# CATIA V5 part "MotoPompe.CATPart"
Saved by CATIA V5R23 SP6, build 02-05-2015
Part number: MotoPompe
Publications: "CATRouFace1", "CATRouCenter1", "CATRouCircular1", "CATRouDatumPt1", "CATRouFace2", "CATRouCenter2", "CATRouCircular2", "CATRouDatumPt2"
Bounding box of the stored display mesh (mm): x -1200 to 1233.058, y -1160.359 to 1160.359, z -3900 to 3100
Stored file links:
  \\etu.ad.univ-lorraine.fr\bordron1\Documents\Parts EPR\MotoPompe.CATPart
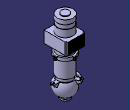
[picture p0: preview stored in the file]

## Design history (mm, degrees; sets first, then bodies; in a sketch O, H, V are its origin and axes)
AxisSystem1: origin (0, 0, 0), X (1, 0, 0), Y (0, 1, 0), Z (0, 0, 1)
Set1
  Point1: type Center, Curve edge [face of Pad8 from Sketch7.A1 | end face of Pad8]
  Line1: type PtDir, RefPoint Point1, Direction edge [XY plane of AxisSystem1 | ZX plane of AxisSystem1], Start -482, End 506
  Point2: type Center, Curve edge [face of Shaft1 from Sketch1.L18 | face of Shaft1 from Sketch1.L17]
  Line2: type PtDir, RefPoint Point2, Direction edge [ZX plane of AxisSystem1 | YZ plane of AxisSystem1], Start -1522, End 506
Body1 (main body)
  Sketch1 on YZ plane of AxisSystem1, origin (0, 0, 0), H (0, 1, 0), V (0, 0, 1)
    line L1 (-750, -300) -> (-750, -1900)
    reference intersected line E1 through (0, 0) direction (0, 1) from ZX plane of AxisSystem1
    line L2 (0, 3100) -> (-375, 3100)
    point P3 (0, 3100)
    line L3 (-375, 3100) -> (-375, 3020)
    line L4 (-375, 3020) -> (-750, 3020)
    point P6 (-750, 3020)
    line L5 (-750, 3020) -> (-750, 2620)
    line L6 (-750, 2620) -> (-710, 2620)
    line L7 (-710, 2620) -> (-710, 2220)
    line L8 (-710, 2220) -> (-750, 2220)
    point P10 (-750, 2220)
    line L9 (-750, 2220) -> (-750, 0)
    line L10 (-750, 0) -> (-900, 0)
    line L11 (-900, 0) -> (-900, -300)
    line L12 (-900, -300) -> (-750, -300)
    line L13 (-750, -1900) -> (-670, -1900)
    line L14 (-670, -1900) -> (-670, -2200)
    line L15 (-670, -2200) -> (-750, -2200)
    point P16 (-750, -2200)
    arc A1 centre (0, -2783.0952) radius 950 from (-750, -2200) to (-548.2292, -3558.9462) ccw
    point P17 (0, -2783.0952)
    line L16 (-442.5, -3763.1175) -> (-442.5, -3900)
    line L17 (-442.5, -3900) -> (-385, -3900)
    line L18 (-385, -3900) -> (-385, -3000)
    line L19 (-385, -3000) -> (0, -3000)
    point P21 (0, -3000)
    reference intersected line E2 through (0, 0) direction (-1, 0) from XY plane of AxisSystem1
    reference intersected line E3 through (0, 0) direction (0, 1) from ZX plane of AxisSystem1
    reference intersected line E4 through (0, 0) direction (0, 1) from ZX plane of AxisSystem1
    reference intersected line E5 through (0, 0) direction (-1, 0) from XY plane of AxisSystem1
    arc A2 centre (-692.5, -3763.1175) radius 250 from (-548.2292, -3558.9462) to (-442.5, -3763.1175) cw
    distance L1 E1 = 750
    distance L17 L2 = 7000
    length L1 = 1600
    length L14 = 300
    length L11 = 300
    length L5 = 400
    length L7 = 400
    distance L2 L4 = 80
    length L2 = 375
    distance L7 L5 = 40
    distance L11 L9 = 150
    distance L1 L14 = 80
    radius A1 = 950
    distance L18 E3 = 385
    distance L16 E4 = 442.5
    length L18 = 900
    distance L19 E5 = 3000
    radius A2 = 250
    vertical: L1 V, L3 V, L5 V, L7 V, L9 V, L11 V, L14 V, L16 V, L18 V
    coincidence: P3 V, P6 L1, P10 L1, P16 L1, P17 V, P21 V, L10 E2
    horizontal: L2 H, L4 H, L6 H, L8 H, L10 H, L12 H, L13 H, L15 H, L17 H, L19 H
    tangency: A2 L16, A2 A1
  Shaft1: profile Sketch1, axis edge [ZX plane of AxisSystem1 | YZ plane of AxisSystem1], angle 360
  Sketch2 on XY plane of AxisSystem1, origin (0, 0, 0), H (1, 0, 0), V (0, 1, 0)
    projected circle E1 centre (0, 0) radius 900 from edge [face of Shaft1 from Sketch1.L11 | face of Shaft1 from Sketch1.L10]
    projected arc E2 centre (0, 0) radius 900 from (885.6636, -160) to (885.6636, 160) ccw from edge [face of Shaft1 from Sketch1.L11 | face of Shaft1 from Sketch1.L10]
    line L1 (958.8327, 148.3022) -> (1044.2788, 76.6044)
    line L2 (958.8327, -148.3022) -> (1044.2788, -76.6044)
    point P2 (1044.2788, -76.6044)
    arc A1 centre (980, 0) radius 100 from (1044.2788, -76.6044) to (1044.2788, 76.6044) ccw
    point P3 (980, 0)
    point P4 (1044.2788, -76.6044)
    line L3 (885.6636, 160) -> (926.6933, 160)
    point P5 (885.6636, 160)
    line L4 (926.6933, -160) -> (885.6636, -160)
    point P6 (885.6636, -160)
    reference intersected line E3 through (0, 0) direction (-1, 0) from ZX plane of AxisSystem1
    arc A2 centre (926.6933, 110) radius 50 from (958.8327, 148.3022) to (926.6933, 160) ccw
    arc A3 centre (926.6933, -110) radius 50 from (958.8327, -148.3022) to (926.6933, -160) cw
    circle A4 centre (980, 0) radius 40
    angle L1 H = 40
    radius A1 = 100
    distance P3 O = 980
    distance L4 L3 = 320
    radius A2 = 50
    radius A3 = 50
    radius A4 = 40
    coincidence: P4 P2, P5 E1, P6 E1
    tangency: A1 L1, L2 A1, A2 L1, A2 L3, A3 L2, A3 L4
    symmetry: L2 L1 H, L4 L3 E3
    horizontal: L3 H, L4 H
  Pad1: profile Sketch2, direction (0, 0, -1), length 90
  Pad2: profile Sketch2, direction (0, 0, 1), up to face of Shaft1 from Sketch1.L12, opposite side length 210
  CircPattern1: of Pad1, Sketch2, Pad2, Sketch2, instances 4, angular step 90, axis from edge [ZX plane of AxisSystem1 | YZ plane of AxisSystem1]
  Sketch3 on YZ plane of AxisSystem1, origin (0, 0, 0), H (0, 1, 0), V (0, 0, 1)
    line L1 (-1100, 1550) -> (900, 1550)
    line L2 (900, 1550) -> (900, 450)
    line L3 (900, 450) -> (-1100, 450)
    line L4 (-1100, 450) -> (-1100, 1550)
    distance H L3 = 450
    length L4 = 1100
    distance L4 V = 1100
    distance L2 V = 900
    horizontal: L1 H, L3 H
    vertical: L2 V, L4 V
  Pad3: profile Sketch3, direction (1, 0, 0), length 900, mirrored extent
  Sketch4 on face of Pad3 from Sketch3.L2, origin (0, 900, 0), H (-1, 0, 0), V (0, 0, 1)
    projected line E1 (900, 1550) -> (-900, 1550) from edge [face of Pad3 from Sketch3.L1 | face of Pad3 from Sketch3.L2]
    projected line E2 (900, 450) -> (-900, 450) from edge [face of Pad3 from Sketch3.L2 | face of Pad3 from Sketch3.L3]
    point P5 (-787.626, 1550)
    point P6 (-787.626, 450)
    line L1 (-787.626, 1550) -> (0, 1550)
    point P7 (0, 1550)
    line L2 (-787.626, 450) -> (0, 450)
    point P8 (0, 450)
    point P9 (-714, 1490)
    point P10 (-714, 510)
    line L3 (-714, 510) -> (-655, 510)
    point P11 (0, 510)
    line L4 (-714, 1490) -> (-655, 1490)
    point P12 (0, 1490)
    line L5 (-655, 1490) -> (-655, 510)
    point P13 (-655, 1490)
    point P14 (-655, 510)
    line L6 (-633, 510) -> (-633, 1490)
    point P15 (-633, 510)
    point P16 (-633, 1490)
    line L7 (-563, 1490) -> (-563, 510)
    point P17 (-563, 1490)
    point P18 (-563, 510)
    line L8 (-541, 510) -> (-541, 1490)
    point P19 (-541, 510)
    point P20 (-541, 1490)
    line L9 (-471, 1490) -> (-471, 510)
    point P21 (-471, 1490)
    point P22 (-471, 510)
    line L10 (-449, 510) -> (-449, 1490)
    point P23 (-449, 510)
    point P24 (-449, 1490)
    line L11 (-379, 1490) -> (-379, 510)
    point P25 (-379, 1490)
    point P26 (-379, 510)
    line L12 (-357, 510) -> (-357, 1490)
    point P27 (-357, 510)
    point P28 (-357, 1490)
    line L13 (-287, 1490) -> (-287, 510)
    point P29 (-287, 1490)
    point P30 (-287, 510)
    line L14 (-265, 510) -> (-265, 1490)
    point P31 (-265, 510)
    point P32 (-265, 1490)
    line L15 (-195, 1490) -> (-195, 510)
    point P33 (-195, 1490)
    point P34 (-195, 510)
    line L16 (-173, 510) -> (-173, 1490)
    point P35 (-173, 510)
    point P36 (-173, 1490)
    line L17 (-103, 1490) -> (-103, 510)
    point P37 (-103, 1490)
    point P38 (-103, 510)
    line L18 (-81, 510) -> (-81, 1490)
    point P39 (-81, 510)
    point P40 (-81, 1490)
    line L19 (-714, 1490) -> (-714, 510)
    line L20 (-11, 1490) -> (-11, 510)
    point P41 (-11, 1490)
    point P42 (-11, 510)
    reference projected line E3 through (0, 0) direction (0, 1) from edge [ZX plane of AxisSystem1 | YZ plane of AxisSystem1]
    point P45 (787.626, 450)
    point P46 (787.626, 1550)
    line L21 (-633, 1490) -> (-563, 1490)
    line L22 (-541, 1490) -> (-471, 1490)
    line L23 (-449, 1490) -> (-379, 1490)
    line L24 (-357, 1490) -> (-287, 1490)
    line L25 (-265, 1490) -> (-195, 1490)
    line L26 (-173, 1490) -> (-103, 1490)
    line L27 (-81, 1490) -> (-11, 1490)
    line L28 (-81, 510) -> (-11, 510)
    line L29 (-173, 510) -> (-103, 510)
    line L30 (-265, 510) -> (-195, 510)
    line L31 (-357, 510) -> (-287, 510)
    line L32 (-449, 510) -> (-379, 510)
    line L33 (-541, 510) -> (-471, 510)
    line L34 (-633, 510) -> (-563, 510)
    reference intersected line E4 through (0, 0) direction (0, -1) from YZ plane of AxisSystem1
    point P49 (714, 1490)
    point P50 (714, 510)
    point P51 (0, 510)
    point P52 (0, 1490)
    point P53 (655, 1490)
    point P54 (655, 510)
    point P55 (633, 510)
    point P56 (633, 1490)
    point P57 (563, 1490)
    point P58 (563, 510)
    point P59 (541, 510)
    point P60 (541, 1490)
    point P61 (471, 1490)
    point P62 (471, 510)
    point P63 (449, 510)
    point P64 (449, 1490)
    point P65 (379, 1490)
    point P66 (379, 510)
    point P67 (357, 510)
    point P68 (357, 1490)
    point P69 (287, 1490)
    point P70 (287, 510)
    point P71 (265, 510)
    point P72 (265, 1490)
    point P73 (195, 1490)
    point P74 (195, 510)
    point P75 (173, 510)
    point P76 (173, 1490)
    point P77 (103, 1490)
    point P78 (103, 510)
    point P79 (81, 510)
    point P80 (81, 1490)
    point P81 (11, 1490)
    point P82 (11, 510)
    line L35 (714, 510) -> (655, 510)
    line L36 (714, 1490) -> (655, 1490)
    line L37 (655, 1490) -> (655, 510)
    line L38 (633, 510) -> (633, 1490)
    line L39 (563, 1490) -> (563, 510)
    line L40 (541, 510) -> (541, 1490)
    line L41 (471, 1490) -> (471, 510)
    line L42 (449, 510) -> (449, 1490)
    line L43 (379, 1490) -> (379, 510)
    line L44 (357, 510) -> (357, 1490)
    line L45 (287, 1490) -> (287, 510)
    line L46 (265, 510) -> (265, 1490)
    line L47 (195, 1490) -> (195, 510)
    line L48 (173, 510) -> (173, 1490)
    line L49 (103, 1490) -> (103, 510)
    line L50 (81, 510) -> (81, 1490)
    line L51 (714, 1490) -> (714, 510)
    line L52 (11, 1490) -> (11, 510)
    line L53 (633, 1490) -> (563, 1490)
    line L54 (541, 1490) -> (471, 1490)
    line L55 (449, 1490) -> (379, 1490)
    line L56 (357, 1490) -> (287, 1490)
    line L57 (265, 1490) -> (195, 1490)
    line L58 (173, 1490) -> (103, 1490)
    line L59 (81, 1490) -> (11, 1490)
    line L60 (81, 510) -> (11, 510)
    line L61 (173, 510) -> (103, 510)
    line L62 (265, 510) -> (195, 510)
    line L63 (357, 510) -> (287, 510)
    line L64 (449, 510) -> (379, 510)
    line L65 (541, 510) -> (471, 510)
    line L66 (633, 510) -> (563, 510)
    line L67 (-787.626, 1550) -> (-787.626, 450)
    line L68 (787.626, 1550) -> (787.626, 450)
    line L69 (0, 1550) -> (787.626, 1550)
    line L70 (787.626, 450) -> (0, 450)
    distance L5 L6 = 22
    distance L6 L7 = 70
    distance L8 L7 = 22
    distance L8 L9 = 70
    distance L9 L10 = 22
    distance L10 L11 = 70
    distance L11 L12 = 22
    distance L12 L13 = 70
    distance L13 L14 = 22
    distance L14 L15 = 70
    distance L15 L16 = 22
    distance L16 L17 = 70
    distance L17 L18 = 22
    distance L18 L20 = 70
    distance L20 P12 = 11
    distance L3 L2 = 60
    distance L4 L1 = 60
    coincidence: P5 E1, P6 E2, P11 V, P12 V, P15 L3, P16 L4, P17 L4, P19 L3, P20 L4, P21 L4, P23 L3, P24 L4, P25 L4, P29 L4, P31 L3, P32 L4, P33 L4, P35 L3, P36 L4, P37 L4, P39 L3, P40 L4, P41 L4, P42 L3, L4 P28, L4 L21, L21 L22, L22 L23, L23 L24, L24 L25, L25 L26, L26 L27, L3 P27, L3 L28, L3 L29, L3 L30, L3 L31, L3 L32, L3 L33, L3 L34
    midpoint: P7 E1, P8 E2
    horizontal: L1 H, L2 H, L3 H, L4 H, L21 H, L22 H, L23 H, L24 H, L25 H, L26 H, L27 H, L28 H, L29 H, L30 H, L31 H, L32 H, L33 H, L34 H, L69 H, L70 H
    vertical: L5 V, L6 V, L7 V, L8 V, L9 V, L10 V, L11 V, L12 V, L13 V, L14 V, L15 V, L16 V, L17 V, L18 V, L19 V, L20 V, L67 V, L68 V
    symmetry: P6 P45 E3, P5 P46 E3, P9 P49 E4, P10 P50 E4, P11 P51 E4, P12 P52 E4, P13 P53 E4, P14 P54 E4, P15 P55 E4, P16 P56 E4, P17 P57 E4, P18 P58 E4, P19 P59 E4, P20 P60 E4, P21 P61 E4, P22 P62 E4, P23 P63 E4, P24 P64 E4, P25 P65 E4, P26 P66 E4, P27 P67 E4, P28 P68 E4, P29 P69 E4, P30 P70 E4, P31 P71 E4, P32 P72 E4, P33 P73 E4, P34 P74 E4, P35 P75 E4, P36 P76 E4, P37 P77 E4, P38 P78 E4, P39 P79 E4, P40 P80 E4, P41 P81 E4, P42 P82 E4, L3 L35 E4, L4 L36 E4, L5 L37 E4, L6 L38 E4, L7 L39 E4, L8 L40 E4, L9 L41 E4, L10 L42 E4, L11 L43 E4, L12 L44 E4, L13 L45 E4, L14 L46 E4, L15 L47 E4, L16 L48 E4, L17 L49 E4, L18 L50 E4, L19 L51 E4, L20 L52 E4, L21 L53 E4, L22 L54 E4, L23 L55 E4, L24 L56 E4, L25 L57 E4, L26 L58 E4, L27 L59 E4, L28 L60 E4, L29 L61 E4, L30 L62 E4, L31 L63 E4, L32 L64 E4, L33 L65 E4, L34 L66 E4
    equidistance: P9 P12 P28, P10 P11 P27
  Pad4: profile Sketch4, direction (0, 1, 0), length 150
  Sketch5 on face of Shaft1 from Sketch1.L15, origin (0, 0, -2200), H (1, 0, 0), V (0, 1, 0)
    projected circle E1 centre (0, 0) radius 750 from edge [face of Shaft1 from Sketch1.A1 | face of Shaft1 from Sketch1.L15]
    projected arc E2 centre (0, 0) radius 750 from (726.8253, -185) to (726.8253, 185) ccw from edge [face of Shaft1 from Sketch1.A1 | face of Shaft1 from Sketch1.L15]
    line L1 (726.8253, 185) -> (1233.0577, 185)
    point P1 (726.8253, 185)
    line L2 (726.8253, -185) -> (1233.0577, -185)
    point P3 (726.8253, -185)
    line L3 (1233.0577, 185) -> (1233.0577, -185)
    circle A1 centre (1092.9949, 0) radius 80
    point P5 (1092.9949, 0)
    radius A1 = 80
    length L3 = 370
    coincidence: P1 E1, P3 E1, P5 H
    horizontal: L1 H, L2 H
    vertical: L3 V
    symmetry: L2 L1 H
  Pad5: profile Sketch5, direction (0, 0, -1), length 50
  Sketch6 on face of Pad5 from Sketch5.L1, origin (0, 185, 0), H (-1, 0, 0), V (0, 0, 1)
    projected line E1 (-1233.0577, -2250) -> (-764.2542, -2250) from edge [end face of Pad5 | face of Pad5 from Sketch5.L1]
    line L1 (-1233.0577, -2250) -> (-1233.0577, -2315.899)
    line L2 (-1207.6321, -2359.4433) -> (-892.2621, -2537.4236)
    line L3 (-892.2621, -2537.4236) -> (-764.2542, -2250)
    arc A1 centre (-1183.0577, -2315.899) radius 50 from (-1207.6321, -2359.4433) to (-1233.0577, -2315.899) cw
    radius A1 = 50
    vertical: L1 V
    tangency: A1 L2, A1 L1
  Pad6: profile Sketch6, direction (0, -1, 0), length 30
  Pad7: profile Sketch6, direction (0, 1, 0), up to face of Pad5 from Sketch5.L2, opposite side length 340
  CircPattern2: of Pad5, Sketch5, Pad6, Sketch6, Pad7, Sketch6, instances 3, angular step 120, axis from edge [ZX plane of AxisSystem1 | YZ plane of AxisSystem1]
  Sketch7 on YZ plane of AxisSystem1, origin (0, 0, 0), H (0, 1, 0), V (0, 0, 1)
    circle A1 centre (0, -2833.1978) radius 385
    point P1 (0, -2833.1978)
    circle A2 centre (0, -2833.1978) radius 442.5
    radius A1 = 385
    radius A2 = 442.5
    coincidence: P1 V
  Pad8: profile Sketch7, direction (-1, 0, 0), length 1200, opposite side length -700
  Fillet1: radius 200, on edge [face of Shaft1 from Sketch1.A1 | face of Pad8 from Sketch7.A2]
